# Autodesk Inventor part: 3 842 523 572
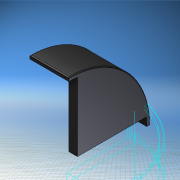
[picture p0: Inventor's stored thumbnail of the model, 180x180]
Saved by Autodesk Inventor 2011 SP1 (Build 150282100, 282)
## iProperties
Created: 2011-02
Part Number: 3 842 523 572
Description: ROUND COVER CAP 45X90
Document SubType Name: Modeling
Designer: SRW
Stock Number: 3 842 523 572
Density: 1.32 g/cm^3
Material: Polyaryletherketone Resin
Mass: 84.6757 g
Surface Area: 220.444 cm^2
Volume: 64.1482 cm^3
Author: SRW
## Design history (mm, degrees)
feature "Base1"
sketch "Sketch1"
  geometry: L1 (-3, 11.076)-(-74.924, 83) reference; L2 (-74.924, 83)-(-77.503, 85.579); L3 (-3, 11.076)-(-0.421, 8.497); 3 further points
  constraints: 6 end point, 2 collinear, 6 other
extrude "Extrusion1" join sketch "Sketch1" distance "d0" = 4; taper "d1" = 0 deg
body "Solid1"
